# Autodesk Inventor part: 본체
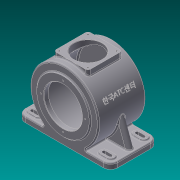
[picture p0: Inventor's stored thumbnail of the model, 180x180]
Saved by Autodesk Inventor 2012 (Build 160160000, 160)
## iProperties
Created: 2015-06
Part Number: 본체
Material: 알루미늄-6061
Document SubType Name: Modeling
Designer: Administrator
Density: 2.71 g/cm^3
Mass: 3273.68 g
Surface Area: 2306.56 cm^2
Volume: 1208 cm^3
Author: Administrator
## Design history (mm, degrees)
sketch "스케치1"
  geometry: L1 (-115, -71)-(-46.733, -71); L2 (-115, -71)-(-115, -85); L3 (-115, -85)-(115, -85); L4 (115, -85)-(115, -71); L5 (-46.733, -71)-(46.733, -71); L6 (46.733, -71)-(115, -71); A1 r 85 centre (0, 0) between (46.733, -71) and (-46.733, -71); 2 further points
  constraints: 12 end point, 4 perpendicular, 3 horizontal, 2 point on circle, 1 centre point, 1 coincident, 1 parallel, 1 point on line, 1 vertical alignment
  dimensions: "d0" = 170 diameter of A1; "d15" = 230 distance between parallel lines of L4 L2; "d16" = 14 distance between parallel lines of L3 L1; "d17" = 85 distance from line of L3 point (0, 0); "d19" = 115 horizontal distance of point (0, 0) L1.start
extrude "돌출4" new body sketch "스케치1" stored distance "d20" = 118; taper "d21" = 0 deg
sketch "스케치5"
  geometry: C1 r 65 at (0, 0); A1 r 85 centre (0, 0) between (46.733, -71) and (-46.733, -71) reference
  constraints: 1 centre point, 1 coincident
  dimensions: "d22" = 130 diameter of C1
extrude "돌출5" join sketch "스케치5" distance "d23" = 3; taper "d24" = 0 deg
hole "구멍1" diameter "d27" = 95; stored, may be unused: countersink angle "d31" = 90 deg, drill point angle "d33" = 0 deg; dims "d25" = 10, "d26" = 10, "d28" = 6, "d29" = 4, "d30" = 2, "d32" = 11
sketch "스케치6"
  geometry: C1 r 65 at (0, 0); A1 r 85 centre (0, 0) between (-46.733, 71) and (46.733, 71) reference
  constraints: 1 centre point, 1 coincident
  dimensions: "d34" = 130 diameter of C1
extrude "돌출6" join sketch "스케치6" distance "d35" = 13; taper "d36" = 0 deg
hole "구멍2" diameter "d39" = 154; stored, may be unused: countersink angle "d43" = 90 deg, drill point angle "d45" = 0 deg; dims "d37" = 10, "d38" = 10, "d40" = 6, "d41" = 4, "d42" = 2, "d44" = 102
sketch "스케치7"
  geometry: C1 r 77 at (0, 0) reference; C2 r 31 at (0, 0)
  constraints: 1 centre point, 1 coincident
  dimensions: "d46" = 62 diameter of C2
extrude "돌출7" join sketch "스케치7" distance "d47" = 3.5; taper "d48" = 0 deg
hole "구멍3" diameter "d51" = 47; stored, may be unused: countersink angle "d55" = 90 deg, drill point angle "d57" = 0 deg; dims "d49" = 10, "d50" = 10, "d52" = 6, "d53" = 4, "d54" = 2, "d56" = 14
hole "구멍4" diameter "d60" = 30; stored, may be unused: countersink angle "d64" = 90 deg, drill point angle "d66" = 0 deg; dims "d58" = 10, "d59" = 10, "d61" = 6, "d62" = 4, "d63" = 2, "d65" = 3
node "작업 평면3"
sketch "스케치8"
  geometry: L1 (-42.5, 42.5)-(42.5, 42.5); L2 (42.5, 42.5)-(42.5, -42.5); L3 (42.5, -42.5)-(-42.5, -42.5); L4 (-42.5, -42.5)-(-42.5, 42.5); L5 (-42.5, -42.5)-(42.5, 42.5); 2 further points
  constraints: 10 end point, 2 parallel, 2 perpendicular, 1 coincident, 1 horizontal, 1 midpoint
  dimensions: "d68" = 85 distance between parallel lines of L4 L2
extrude "돌출8" join sketch "스케치8" stored distance "d69" = 3.5; taper "d70" = 0 deg
hole "구멍5" diameter "d73" = 70; stored, may be unused: countersink angle "d77" = 90 deg, drill point angle "d79" = 0 deg; dims "d71" = 42.5, "d72" = 42.5, "d74" = 6, "d75" = 4, "d76" = 2, "d78" = 3
sketch "스케치9"
  geometry: L1 (42.5, 88)-(42.5, 73.612) reference; L2 (46.733, -71)-(115, -71) reference; L3 (115, -71)-(115, -85) reference; L4 (115, -85)-(-115, -85) reference; L5 (-115, -85)-(-115, -71) reference; L6 (-115, -71)-(-46.733, -71) reference; L7 (-42.5, 73.612)-(-42.5, 88) reference; L8 (-42.5, 88)-(-35, 88) reference; L9 (-35, 88)-(-35, 68.586) reference; L10 (35, 68.586)-(35, 88) reference; L11 (35, 88)-(42.5, 88) reference; L12 (-84.87, -4.703)-(-109, -71); A1 r 85 centre (0, 0) between (46.733, -71) and (42.5, 73.612) reference; A2 r 85 centre (0, 0) between (-42.5, 73.612) and (-46.733, -71) reference; A3 r 77 centre (0, 0) between (-35, 68.586) and (35, 68.586) reference; 1 further point
  constraints: 2 end point, 1 point on circle, 1 point on line
  dimensions: "d80" = 6 distance from line of L12.end L5; "d81" = 110 deg angle of L6 L12
feature "리브1" sketch "스케치9" dims "d82" = 1, "d83" = 15, "d84" = 0, "d85" = 0, "d86" = 1, "d87" = 1
sketch "스케치10"
  geometry: L1 (68.267, 0)-(0, 0) reference; L2 (34.267, -9)-(50.267, -9); L3 (34.267, -27)-(50.267, -27); L4 (-161.733, -118)-(-161.733, 0) reference; L5 (-161.733, 0)-(-93.467, 0) reference; L6 (-93.467, -118)-(-93.467, 0) reference; L7 (0, -118)-(-93.467, -118) reference; L8 (0, -66.5)-(0, -118) reference; L9 (62.267, -66.5)-(0, -66.5) reference; L10 (62.267, -51.5)-(62.267, -66.5) reference; L11 (0, -51.5)-(62.267, -51.5) reference; L12 (0, 0)-(0, -51.5) reference; L13 (0, 0)-(68.267, 0) reference; L14 (68.267, 0)-(68.267, -118) reference; L15 (68.267, -118)-(0, -118) reference; L16 (-93.467, -118)-(-161.733, -118) reference; L17 (-93.467, 0)-(0, 0) reference; L18 (-76.533, -8)-(-76.533, -110) reference; L19 (-76.533, -110)-(-16.934, -110) reference; L20 (-16.934, -110)-(-16.934, -8) reference; L21 (-16.934, -8)-(-76.533, -8) reference; L22 (34.267, -91)-(50.267, -91); L23 (34.267, -109)-(50.267, -109); L24 (-143.733, -109)-(-127.733, -109); L25 (-143.733, -91)-(-127.733, -91); L26 (-143.733, -9)-(-127.733, -9); L27 (-143.733, -27)-(-127.733, -27); A1 r 9 centre (50.267, -18) between (50.267, -27) and (50.267, -9); A2 r 9 centre (34.267, -18) between (34.267, -9) and (34.267, -27); A3 r 9 centre (-127.733, -18) between (-127.733, -27) and (-127.733, -9); A4 r 9 centre (-143.733, -18) between (-143.733, -9) and (-143.733, -27); A5 r 9 centre (-127.733, -100) between (-127.733, -109) and (-127.733, -91); A6 r 9 centre (-143.733, -100) between (-143.733, -91) and (-143.733, -109); A7 r 9 centre (50.267, -100) between (50.267, -109) and (50.267, -91); A8 r 9 centre (34.267, -100) between (34.267, -91) and (34.267, -109); 1 further point
  constraints: 16 end point, 16 point on circle, 16 tangent, 8 centre point, 6 horizontal alignment, 5 equal length, 4 equal radius, 2 vertical alignment
  dimensions: "d88" = 18 diameter of A1; "d89" = 16 distance of A1.centre A2.centre; "d90" = 97 horizontal distance of A1.centre point (-46.733, -59); "d91" = 18 distance from line of L1 A1.centre; "d99" = 18 diameter of A3; "d100" = 16 distance of A3.centre A4.centre; "d101" = 18 diameter of A5; "d102" = 16 distance of A5.centre A6.centre; "d103" = 18 diameter of A7; "d104" = 16 distance of A7.centre A8.centre; "d105" = 18 distance from line of L15 A7.centre; "d108" = 97 horizontal distance of point (-46.733, -59) A6.centre (= d90)
extrude "돌출11" join sketch "스케치10" distance "d109" = 3; taper "d110" = 0 deg
sketch "스케치12"
  geometry: L1 (50.267, -109)-(34.267, -109) reference; L2 (34.267, -91)-(50.267, -91) reference; L3 (34.267, -9)-(50.267, -9) reference; L4 (50.267, -27)-(34.267, -27) reference; L5 (-127.733, -109)-(-143.733, -109) reference; L6 (-143.733, -91)-(-127.733, -91) reference; L7 (-127.733, -27)-(-143.733, -27) reference; L8 (-143.733, -9)-(-127.733, -9) reference; L9 (4.267, -66.5)-(4.267, -118) reference; L10 (4.267, -118)-(-97.733, -118) reference; L11 (-97.733, -118)-(-97.733, 0) reference; L12 (-97.733, 0)-(4.267, 0) reference; L13 (4.267, 0)-(4.267, -51.5) reference; L14 (4.267, -51.5)-(61.175, -51.5) reference; L15 (61.175, -51.5)-(61.175, -66.5) reference; L16 (61.175, -66.5)-(4.267, -66.5) reference; L17 (-82.858, -8)-(-82.858, -110) reference; L18 (-82.858, -110)-(-10.609, -110) reference; L19 (-10.609, -110)-(-10.609, -8) reference; L20 (-10.609, -8)-(-82.858, -8) reference; L21 (-127.733, -14)-(-143.733, -14); L22 (-143.733, -22)-(-127.733, -22); L23 (50.267, -14)-(34.267, -14); L24 (34.267, -22)-(50.267, -22); L25 (50.267, -96)-(34.267, -96); L26 (34.267, -104)-(50.267, -104); L27 (-143.733, -100)-(-127.733, -100); L28 (-143.733, -96)-(-127.733, -96); L29 (-143.733, -104)-(-127.733, -104); A1 r 9 centre (34.267, -100) between (34.267, -91) and (34.267, -109) reference; A2 r 9 centre (50.267, -100) between (50.267, -109) and (50.267, -91) reference; A3 r 9 centre (50.267, -18) between (50.267, -27) and (50.267, -9) reference; A4 r 9 centre (34.267, -18) between (34.267, -9) and (34.267, -27) reference; A5 r 9 centre (-143.733, -100) between (-143.733, -91) and (-143.733, -109) reference; A6 r 9 centre (-127.733, -100) between (-127.733, -109) and (-127.733, -91) reference; A7 r 9 centre (-143.733, -18) between (-143.733, -9) and (-143.733, -27) reference; A8 r 9 centre (-127.733, -18) between (-127.733, -27) and (-127.733, -9) reference; A9 r 4 centre (-143.733, -18) between (-143.733, -14) and (-143.733, -22); A10 r 4 centre (-127.733, -18) between (-127.733, -22) and (-127.733, -14); A11 r 4 centre (34.267, -18) between (34.267, -14) and (34.267, -22); A12 r 4 centre (50.267, -18) between (50.267, -22) and (50.267, -14); A13 r 4 centre (34.267, -100) between (34.267, -96) and (34.267, -104); A14 r 4 centre (50.267, -100) between (50.267, -104) and (50.267, -96); A15 r 4 centre (-143.733, -100) between (-143.733, -96) and (-143.733, -104); A16 r 4 centre (-127.733, -100) between (-127.733, -104) and (-127.733, -96); 1 further point
  constraints: 18 end point, 16 point on circle, 8 centre point, 2 coincident, 2 parallel, 2 tangent, 9 other
  dimensions: "d111" = 5 distance between parallel lines of L8 L21; "d114" = 5 distance between parallel lines of L3 L23; "d115" = 5 distance between parallel lines of L2 L25; "d116" = 8 diameter of A15; "d117" = 8 diameter of A16; "d118" = 16 distance of L29.start L29.end
extrude "돌출12" cut sketch "스케치12" stored distance "d119" = 3; taper "d120" = 0 deg
node "작업 평면5"
  node "작업 평면4"
sketch "스케치13"
  geometry: L1 (-40.533, 6.549)-(40.533, 6.549); L2 (40.533, 6.549)-(40.533, -6.549); L3 (40.533, -6.549)-(-40.533, -6.549); L4 (-40.533, -6.549)-(-40.533, 6.549); L5 (-40.533, -6.549)-(40.533, 6.549); 2 further points
  constraints: 2 end point, 1 coincident, 1 midpoint, 2 other
feature "엠보싱1" sketch "스케치13" dims "d27" = 95, "d29" = 4, "d30" = 2, "d32" = 11, "d123" = 0.5, "d124" = 0
sketch "스케치14" dims "d125" = 110
  geometry: C1 r 47.5 at (0, 0) reference; C2 r 65 at (0, 0) reference; 2 further points
  constraints: 2 vertical alignment, 1 coincident, 2 other
hole "구멍6" sketch "스케치14" at (0, 55) diameter "d126" = 3.242; stored, may be unused: countersink angle "d130" = 90 deg, drill point angle "d132" = 118 deg; dims "d127" = 6, "d128" = 4, "d129" = 2, "d131" = 3
sketch "스케치15"
  geometry: L1 (0, 0)-(-35, 0); L2 (0, 0)-(0, 35); A1 r 35 centre (0, 0) between (-35, 0) and (0, 35) reference; 4 further points
  constraints: 4 end point, 2 point on circle, 2 symmetric about line, 1 horizontal alignment, 1 perpendicular, 1 vertical, 1 vertical alignment
  dimensions: "d136" = 71 distance of point (-35.5, -35.5) point (-35.5, 35.5); "d137" = 71 distance of point (-35.5, 35.5) point (35.5, 35.5)
hole "구멍7" sketch "스케치15" at (-35.5, 35.5), (35.5, 35.5), (35.5, -35.5), (-35.5, -35.5) diameter "d138" = 3.242; stored, may be unused: countersink angle "d142" = 90 deg, drill point angle "d144" = 118 deg; dims "d139" = 10, "d140" = 4, "d141" = 2, "d143" = 13
fillet "모깎기1" dims "d145" = 18
fillet "모깎기2" dims "d146" = 7
feature "면 기울기1" dims angle "d147" = 25 deg
fillet "모깎기3" dims "d148" = 0.3
fillet "모깎기4" dims "d149" = 3
chamfer "모따기1" distance "d150" = 1; stored, may be unused: second distance "d151" = 2, angle "d152" = 45 deg
fillet "모깎기5" dims "d153" = 7.5
fillet "모깎기6" dims "d154" = 3
fillet "모깎기7" dims "d155" = 3
fillet "모깎기8" dims "d156" = 3
fillet "모깎기9" dims "d157" = 3
node "솔리드2"
pattern_circular "원형 패턴1" dims angle "d134" = 360 deg
mirror "대칭2"
node "절단 모서리 투영2"
node "절단 모서리 투영3"
node "절단 모서리 투영4"
other parameters: "d67" = 88, "d121" = -25 deg, "d122" = 85
